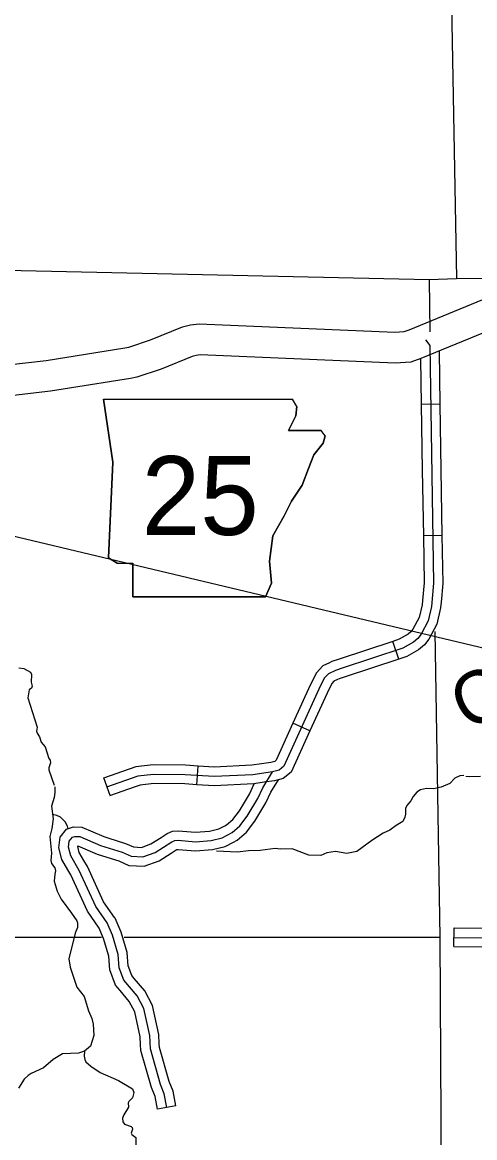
# Model space of a CAD drawing. Extents: x 1212896 to 1368412, y 378476 to 478763.
# Drawn here: x 1285690 to 1289328, y 399509 to 408473 of the extents above; entities that cross this region are included whole.
import ezdxf

# ---------------------------------------------------------------- set-up
doc = ezdxf.new("R2010")
doc.units = 0
for name, color, linetype in [('Level 10', 7, 'Continuous'), ('Level 21', 7, 'Continuous'), ('Level 35', 7, 'Continuous'), ('Level 4', 7, 'Continuous'), ('Level 45', 7, 'Continuous'), ('Level 46', 7, 'Continuous'), ('Level 49', 7, 'Continuous'), ('Level 5', 7, 'Continuous'), ('R_Draft', 7, 'Continuous')]:
    doc.layers.add(name, color=color, linetype=linetype)

msp = doc.modelspace()

# ---------------------------------------------------------------- linework, layer by layer
at = {"layer": 'Level 10'}
msp.add_line((1288894.8, 405770.7), (1288889.5, 405768.6), dxfattribs=at)
for points in [[(1288799.9, 406002), (1289849, 406432.6)], [(1289961.4, 406208.5), (1288894.8, 405770.7)], [(1283293.8, 404003.6), (1283364.1, 404208.2), (1283427.9, 404357.2), (1283477.8, 404425.9), (1283867.6, 404849.5), (1284035.8, 405014.5), (1284233.6, 405171.1), (1284551.3, 405434.9), (1284670.5, 405503.2), (1284892.7, 405606.5), (1285044.4, 405647), (1285262.1, 405684.1), (1285881.5, 405756), (1286514.4, 405856.4), (1286545.4, 405862.7), (1286720.2, 405921.1), (1286977.6, 406025.7), (1287043, 406042.5), (1287111.1, 406050.1), (1288685.3, 405982.7), (1288760.8, 405988.1), (1288799.9, 406002)], [(1288894.8, 405770.7), (1288812.7, 405741.2), (1288688.8, 405732.4), (1287119.7, 405799.5), (1287088.2, 405796), (1287056.1, 405787.7), (1286806.9, 405686.5), (1286609.9, 405620.6), (1286558.6, 405610.3), (1285915.5, 405508.3), (1285297.6, 405436.6), (1285097.8, 405402.5), (1284978.3, 405370.6), (1284785.5, 405281), (1284694.4, 405228.8), (1284391, 404976.9), (1284201.4, 404826.7), (1284047.2, 404675.5), (1283671.6, 404267.3), (1283646.7, 404233), (1283597.5, 404118.2), (1283530.8, 403924.2)]]:
    msp.add_lwpolyline(points, dxfattribs=at)
at = {"layer": 'Level 21'}
for p, q in [((1286341.4, 405445.6), (1286417.5, 404938.1)), ((1287897.9, 405386.4), (1287862.8, 405444.9)), ((1287889.4, 405310.3), (1287897.9, 405386.4)), ((1287830.2, 405191.9), (1287889.4, 405310.3)), ((1288092.4, 405191.9), (1287830.2, 405191.9)), ((1288126.3, 405149.6), (1288092.4, 405191.9)), ((1288033.2, 404997.3), (1288109.3, 405090.4)), ((1288109.3, 405090.4), (1288126.3, 405149.6)), ((1287990.9, 404887.3), (1288033.2, 404997.3)), ((1286417.5, 404938.1), (1286383.7, 404168.3)), ((1287940.2, 404752), (1287990.9, 404887.3)), ((1287855.6, 404625.1), (1287940.2, 404752)), ((1287796.4, 404506.7), (1287855.6, 404625.1)), ((1287703.3, 404346), (1287796.4, 404506.7)), ((1287677.9, 404142.9), (1287703.3, 404346)), ((1286383.7, 404168.3), (1286451.4, 404126)), ((1286451.4, 404126), (1286578.3, 404126)), ((1286578.3, 404126), (1286578.3, 403855.3)), ((1287694.8, 403965.3), (1287677.9, 404142.9)), ((1287644.1, 403855.3), (1287694.8, 403965.3)), ((1286578.3, 403855.3), (1287644.1, 403855.3))]:
    msp.add_line(p, q, dxfattribs=at)
msp.add_lwpolyline([(1286341.4, 405445.6), (1287862.8, 405444.9)], dxfattribs=at)
at = {"layer": 'Level 35'}
for points in [[(1285661.2, 403285.9), (1285702.2, 403279.3), (1285755, 403251.4), (1285763.6, 403231.8), (1285761.1, 403170.8), (1285769.5, 403136.7), (1285763.6, 403120.6), (1285745.8, 403109.4), (1285734.5, 403045.2), (1285808.7, 402809.5), (1285805.1, 402775.4), (1285809.2, 402760.4), (1285828.5, 402731.6), (1285840.9, 402688.6), (1285874.2, 402650.9), (1285904.1, 402556), (1285914.2, 402542.1), (1285915.4, 402523.1), (1285903.8, 402481.9), (1285904, 402464.8), (1285946.3, 402342.6)], [(1289239, 402419.4), (1289208, 402418.2), (1289167.3, 402397.8), (1289127.9, 402356.3), (1289058.4, 402325.4), (1288995.7, 402312.7), (1288939.8, 402316.2), (1288892, 402305.6), (1288861.3, 402287.2), (1288832.7, 402249.9), (1288815.1, 402216.6), (1288781.6, 402178.2), (1288770.1, 402153.8), (1288771.3, 402108.9), (1288765.6, 402084.6), (1288749, 402050.6), (1288695.4, 402018.9), (1288644, 401981.3), (1288591.3, 401957.7), (1288500.2, 401898.6), (1288378.4, 401809.1), (1288299.8, 401792.2), (1288208.8, 401809), (1288138.1, 401798.5), (1288090.5, 401776.9), (1287993.7, 401780.9), (1287858.4, 401829.4), (1287764.9, 401826.9), (1287721.8, 401832.5), (1287602.3, 401817.8), (1287508.6, 401815.8), (1287419.9, 401802.8), (1287250.6, 401811)], [(1289374.7, 402411), (1289282.1, 402408.1), (1289254.9, 402412.6)], [(1285950.2, 402328.1), (1285952.4, 402282.1), (1285947.2, 402242.9), (1285925.7, 402173.1), (1285936.9, 402072.4), (1285927.8, 401994.1), (1285911.5, 401929.8), (1285923.8, 401796.7), (1285920.4, 401735.6), (1285924.7, 401712.6), (1285952, 401676.8), (1285957.5, 401652.9), (1285950.5, 401626.7), (1285946.1, 401570.5), (1285970.8, 401491.6), (1286002.4, 401426.8), (1286086.3, 401314.5), (1286128.9, 401252.8), (1286134.8, 401237), (1286133.4, 401199.8), (1286113.9, 401153.5), (1286065.2, 400946.5), (1286073.8, 400879.5), (1286128.3, 400719.7), (1286186, 400643.2), (1286223.1, 400528.4), (1286248.6, 400468.5), (1286259.1, 400420.6), (1286266, 400329.4)], [(1286057.9, 401991.5), (1286053.3, 402011.5), (1286034.9, 402047.4), (1285995.7, 402085.1), (1285968.7, 402098.8), (1285931.6, 402105.4)], [(1286266, 400329.4), (1286236.9, 400244.5), (1286189.5, 400204), (1286140.4, 400187.6), (1286012.7, 400183.8), (1285937.5, 400138.2), (1285860.5, 400071.2), (1285759.7, 400025.9), (1285736.1, 400010.3), (1285705.9, 399978.6), (1285658.5, 399908.4)], [(1286189.5, 400204), (1286186.8, 400163.5), (1286192.4, 400136.6), (1286201.8, 400119.8), (1286241.5, 400083.5), (1286316.4, 400033), (1286463.5, 399970.1), (1286576.8, 399902.4), (1286587.4, 399872.6), (1286576.4, 399829.2), (1286547.1, 399800.5), (1286542.3, 399788.4), (1286544.1, 399753.3), (1286505.5, 399693.4), (1286496, 399666.5), (1286497.8, 399636.1), (1286511.2, 399617.3), (1286564.4, 399599.4), (1286573.6, 399590.6), (1286574.9, 399576.6), (1286564.6, 399545.3), (1286569.9, 399534.4), (1286602.3, 399511), (1286603.8, 399442.9)]]:
    msp.add_lwpolyline(points, dxfattribs=at)
at = {"layer": 'Level 4'}
msp.add_lwpolyline([(1277120.8, 406365.1), (1279736.9, 406451.6), (1283499.6, 406513.1), (1283856.6, 406519), (1288960.8, 406405.6), (1289181.1, 406415), (1290422.8, 406415.6)], dxfattribs=at)
at = {"layer": 'Level 45'}
for p, q in [((1289047.4, 405404.6), (1288897.4, 405402.2)), ((1289064.4, 404348.8), (1288914.5, 404346.4)), ((1288716.8, 403355.7), (1288669.9, 403498.2)), ((1288003, 402779.2), (1287866.4, 402841.1)), ((1287093.4, 402345.9), (1287102.7, 402495.6)), ((1286395.1, 402259.9), (1286344.8, 402401.2)), ((1289159.8, 401044.5), (1289161.2, 401194.5))]:
    msp.add_line(p, q, dxfattribs=at)
for points in [[(1288932.8, 405920.3), (1288966.1, 405875.7), (1288997, 403964.7), (1288980.2, 403779.3), (1288954, 403663.2), (1288896.2, 403556.2), (1288870.6, 403520.8), (1288834.8, 403491.6), (1288750.7, 403444.4), (1288261.7, 403283.5), (1288208.3, 403264.8), (1288151.3, 403237.5), (1288117.8, 403202.1), (1288073.8, 403113.4), (1287792.9, 402494.2), (1287754.3, 402463.7), (1287702.6, 402450.1), (1287543.2, 402426.4), (1287232.2, 402411), (1286998.6, 402425.5), (1286745.2, 402428.8), (1286619.7, 402415.4), (1286367.2, 402325.5)], [(1289040.5, 405830.5), (1289047.4, 405404.6)], [(1288891.5, 405769.5), (1288897.4, 405402.2)], [(1288897.4, 405402.2), (1288905.9, 404874.3)], [(1289047.4, 405404.6), (1289055.9, 404876.7)], [(1288905.9, 404874.3), (1288914.5, 404346.4)], [(1289055.9, 404876.7), (1289064.4, 404348.8)], [(1289064.4, 404348.8), (1289070.7, 403961.9), (1289057.2, 403813.6)], [(1288914.5, 404346.4), (1288920.6, 403967.5), (1288907.8, 403827.1)], [(1288907.8, 403827.2), (1288904.6, 403791.2), (1288881.8, 403690.2), (1288831.3, 403596.9), (1288814.5, 403573.7), (1288791.7, 403555), (1288719.8, 403514.6), (1288669.9, 403498.2)], [(1289057.2, 403813.6), (1289053, 403767.8), (1289023.5, 403637.1), (1288958.6, 403516.9), (1288924.6, 403469.9), (1288876.5, 403430.5), (1288780.5, 403376.7), (1288716.8, 403355.7)], [(1288669.9, 403498.2), (1288237.1, 403355.8), (1288179.1, 403335.5), (1288160.4, 403326.5)], [(1288160.4, 403326.5), (1288105.6, 403300.3), (1288054.4, 403246.3), (1288004.8, 403146.2), (1287866.4, 402841.1)], [(1288716.8, 403355.7), (1288285.4, 403213.8), (1288236.5, 403196.6), (1288225.1, 403191.2)], [(1288225.1, 403191.2), (1288195.4, 403177), (1288178.8, 403159.5), (1288140.3, 403081.9), (1288003, 402779.2)], [(1287866.4, 402841.1), (1287731, 402542.6), (1287719.5, 402533.5), (1287687.2, 402525.1), (1287613.1, 402514)], [(1288003, 402779.2), (1287852.5, 402447.5), (1287787.8, 402396.4), (1287717.4, 402377.9), (1287635.3, 402365.7)], [(1286548.1, 402471), (1286341.6, 402397.5)], [(1287102.7, 402495.6), (1287001.5, 402501.9), (1286741.7, 402505.2), (1286602.6, 402490.4), (1286548.1, 402471)], [(1287613.1, 402514), (1287535.7, 402502.5), (1287232.6, 402487.5), (1287102.7, 402495.6)], [(1286714.8, 400330.3), (1286666.8, 400546.8), (1286613.4, 400648), (1286505.8, 400774.9), (1286469.9, 400874.7), (1286459.8, 400982.8), (1286414.3, 401135.7), (1286371.4, 401236.4), (1286279.7, 401367.5), (1286147.7, 401655.8), (1286079.6, 401773.3), (1286061.1, 401843.2), (1286067.2, 401892.8), (1286092.1, 401923.8), (1286112.6, 401930.8), (1286151.5, 401929.3), (1286318.1, 401857.7), (1286493.3, 401802.8), (1286564.4, 401770.5), (1286658.2, 401765.5), (1286758.5, 401800.6), (1286891.4, 401887.3), (1286915.2, 401897.4), (1286943.5, 401900), (1287082.4, 401888.1), (1287207.9, 401897.5), (1287296, 401918.7), (1287376.4, 401960.6), (1287438.4, 402014.8), (1287498.7, 402094.2), (1287583.1, 402234.4), (1287624.1, 402322), (1287702.6, 402450.1)], [(1286598.4, 402329.7), (1286391.9, 402256.2)], [(1287093.4, 402345.9), (1286995.8, 402351.9), (1286748.7, 402355.1), (1286636.2, 402343.1), (1286598.4, 402329.7)], [(1287635.3, 402365.7), (1287550.5, 402353), (1287231.7, 402337.3), (1287093.4, 402345.9)], [(1289161.2, 401194.5), (1289689.2, 401189.6)], [(1289159.8, 401044.5), (1289687.8, 401039.6)], [(1289160.5, 401118.1), (1295871.3, 401056)], [(1286852.5, 399752.1), (1286831.1, 399861.9), (1286801.5, 399937.4), (1286719.4, 400222.3), (1286714.8, 400330.3)]]:
    msp.add_lwpolyline(points, dxfattribs=at)
at = {"layer": 'Level 46'}
msp.add_line((1286924.7, 399766.1), (1286777.5, 399737.5), dxfattribs=at)
for points in [[(1287387.5, 401883.4), (1287418.2, 401899.4), (1287492.5, 401964.3), (1287559.8, 402052.9), (1287648.1, 402199.7), (1287689, 402287.1), (1287749.9, 402386.4)], [(1287318.1, 402016.4), (1287333, 402024.2), (1287382.3, 402067.2), (1287435.4, 402137.1), (1287515.6, 402270.4), (1287554.3, 402353.2)], [(1286056, 401661.8), (1286008.4, 401743.9), (1285983.5, 401837.9), (1285994.1, 401923.7), (1286046.4, 401988.9), (1286101.4, 402007.6), (1286168.5, 402005.2), (1286344.7, 401929.4), (1286378.6, 401918.8)], [(1286805.2, 401922.2), (1286855.3, 401955), (1286896.4, 401972.4), (1286943.3, 401976.6), (1287082.8, 401964.8), (1287196, 401973.2), (1287269, 401990.8), (1287318.1, 402016.4)], [(1286185.8, 401737), (1286148.3, 401801.7), (1286135.9, 401848.3), (1286136.8, 401855.5), (1286292.5, 401788.6), (1286333.7, 401775.7)], [(1286378.6, 401918.8), (1286520.6, 401874.3), (1286582.9, 401846), (1286647.3, 401842.6), (1286724.6, 401869.6), (1286805.2, 401922.2)], [(1286887.1, 401796.6), (1286926.2, 401822.1), (1286933.4, 401825.1), (1286943.8, 401826.1), (1287082.1, 401814.3), (1287219.3, 401824.5), (1287322.1, 401849.2), (1287387.5, 401883.4)], [(1286333.7, 401775.7), (1286467, 401733.9), (1286546.6, 401697.8), (1286668.8, 401691.3), (1286791.3, 401734.1), (1286887.1, 401796.6)], [(1286308.7, 401192.8), (1286213.2, 401329.4), (1286079.7, 401620.7), (1286056, 401661.8)], [(1286431.6, 401278.8), (1286343.9, 401404.3), (1286213.1, 401689.7), (1286185.8, 401737)], [(1286590.5, 400788.8), (1286570.6, 400812.4), (1286542.3, 400890.9), (1286532.4, 400996.9), (1286483.7, 401160.7), (1286436.1, 401272.3), (1286431.6, 401278.8)], [(1286476.1, 400691.8), (1286438.6, 400736), (1286394.7, 400858), (1286384.4, 400968.3), (1286342.4, 401109.7), (1286304.3, 401199.1)], [(1286791.3, 400263.9), (1286788.1, 400339.9), (1286736.5, 400572.4), (1286674.8, 400689.4), (1286590.5, 400788.8)], [(1286641.5, 400257.5), (1286638.8, 400320.3), (1286594.5, 400520.3), (1286549.8, 400604.9), (1286476.1, 400691.8)], [(1286777.5, 399737.5), (1286757.5, 399840.5), (1286729.1, 399912.8), (1286643.5, 400209.9), (1286641.5, 400257.5)], [(1286924.7, 399766.1), (1286902.1, 399882.5), (1286871.3, 399961.1), (1286792.6, 400234.2), (1286791.3, 400263.9)]]:
    msp.add_lwpolyline(points, dxfattribs=at)
at = {"layer": 'Level 49'}
for p, q in [((1286417.5, 404938.1), (1286341.4, 405445.6)), ((1287897.9, 405386.4), (1287889.4, 405310.3)), ((1287889.4, 405310.3), (1287830.2, 405191.9)), ((1287830.2, 405191.9), (1288092.4, 405191.9)), ((1288109.3, 405090.4), (1288033.2, 404997.3)), ((1288126.3, 405149.6), (1288109.3, 405090.4)), ((1288033.2, 404997.3), (1287990.9, 404887.3)), ((1286383.7, 404168.3), (1286417.5, 404938.1)), ((1287990.9, 404887.3), (1287940.2, 404752)), ((1287940.2, 404752), (1287855.6, 404625.1)), ((1287855.6, 404625.1), (1287796.4, 404506.7)), ((1287796.4, 404506.7), (1287703.3, 404346)), ((1287703.3, 404346), (1287677.9, 404142.9)), ((1286451.4, 404126), (1286383.7, 404168.3)), ((1286578.3, 403855.3), (1286578.3, 404126)), ((1287677.9, 404142.9), (1287694.8, 403965.3)), ((1287694.8, 403965.3), (1287644.1, 403855.3)), ((1287644.1, 403855.3), (1286578.3, 403855.3))]:
    msp.add_line(p, q, dxfattribs=at)
msp.add_lwpolyline([(1286341.4, 405445.6), (1287862.8, 405444.9)], dxfattribs=at)
at = {"layer": 'Level 5'}
for points in [[(1289084, 411690), (1289181.1, 406415)], [(1288960.8, 406405.6), (1288967.6, 405986)], [(1289006.8, 403577), (1289046.7, 401121.9)], [(1286508.8, 401121.2), (1289046.7, 401121.9)], [(1289046.7, 401121.9), (1289076.7, 395763.7)], [(1283590.7, 401120.3), (1286325.3, 401121.1)]]:
    msp.add_lwpolyline(points, dxfattribs=at)
at = {"layer": 'R_Draft'}
msp.add_line((1324691.3, 395024.3), (1283954.6, 404739.3), dxfattribs=at)

# ---------------------------------------------------------------- texts
at = {"layer": 'Level 21'}
msp.add_text('25', height=633.6, dxfattribs=at).set_placement((1286649, 404353.1))
at = {"layer": 'Level 35'}
msp.add_text('Cunningham', height=422.4, rotation=26.21431, dxfattribs=at).set_placement((1289268.2, 402770))
at = {"layer": 'Level 49'}
msp.add_text('25', height=633.6, dxfattribs=at).set_placement((1286649, 404353.1))

doc.saveas('drawing.dxf')
